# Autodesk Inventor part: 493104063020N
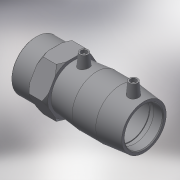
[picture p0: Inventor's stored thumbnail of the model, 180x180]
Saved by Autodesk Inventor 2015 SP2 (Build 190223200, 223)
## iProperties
Created: 2017-06
Part Number: 493104063020N
Material: Generic
Description: PLASSON FEMALE TRANSITION COUPLER 63-2"
Document SubType Name: Modeling
Designer: KIM
Mass: 482.289 g
Surface Area: 878.361 cm^2
Volume: 482.289 cm^3
Density: 1 g/cm^3
Appearance: Default
Author: KIM
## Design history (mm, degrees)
derived "493104.ipt"
feature "Solid1::493104.ipt"
tag "TaggingFeature1"
body "Solid1"
other parameters: "d0" = 117, "d1" = 63, "d2" = 82, "d3" = 57, "d4" = 39, "d5" = 73.8, "d6" = 59.85, "d7" = 63, "d8" = 168 deg, "d10" = 22.8, "d11" = 7.6, "d29" = 58, "d30" = 14, "d31" = 40.95, "d34" = 5 deg, "d41" = 4, "d42" = 14, "d43" = 0, "d48" = 3, "d49" = 0, "d55" = 62, "d57" = 49, "d59" = 56.656, "d60" = 55.8, "d70" = 82, "d71" = 31, "d72" = 0, "d73" = 45 deg, "d74" = 4.9, "d75" = 45 deg, "d77" = 0.945, "d80" = 1.26, "d_" = 63, "L_" = 179, "L_1" = 57, "D_1" = 82, "A_" = 58, "d_2" = 12, "L_2" = 62, "D_" = 49, "R_p" = 56.656
